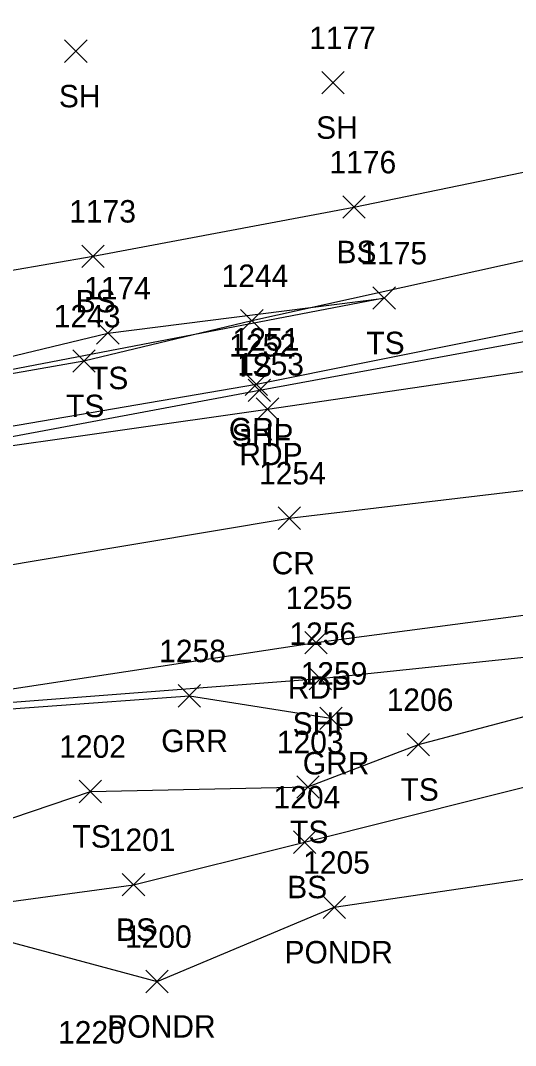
# Model space of a CAD drawing. Extents: x 1497084 to 1499861, y 734741 to 735567.
# Drawn here: x 1498376.8 to 1498420.9, y 735270.8 to 735362.1 of the extents above; entities that cross this region are included whole.
import ezdxf

# ---------------------------------------------------------------- set-up
doc = ezdxf.new("R2010")
doc.units = 0
for name, color, linetype in [('L_A', 7, 'Continuous'), ('L_I', 7, 'Continuous'), ('L_TIC', 7, 'Continuous'), ('LAWE', 7, 'Continuous'), ('LELB', 7, 'Continuous'), ('P_A', 7, 'Continuous'), ('P_I', 7, 'Continuous'), ('P_TIC', 7, 'Continuous'), ('PET', 7, 'Continuous'), ('PRC', 7, 'Continuous'), ('PSP', 7, 'Continuous'), ('R_A', 7, 'Continuous'), ('R_I', 7, 'Continuous'), ('R_TIC', 7, 'Continuous'), ('RGR', 7, 'Continuous')]:
    doc.layers.add(name, color=color, linetype=linetype)

msp = doc.modelspace()

# ---------------------------------------------------------------- linework, layer by layer
at = {"layer": 'L_TIC'}
for points in [[(1498380.723, 735358.388), (1498382.723, 735360.388)], [(1498382.723, 735358.388), (1498380.723, 735360.388)], [(1498403.65, 735355.584), (1498405.65, 735357.584)], [(1498405.65, 735355.584), (1498403.65, 735357.584)], [(1498405.509, 735344.506), (1498407.509, 735346.506)], [(1498407.509, 735344.506), (1498405.509, 735346.506)], [(1498382.259, 735340.124), (1498384.259, 735342.124)], [(1498384.259, 735340.124), (1498382.259, 735342.124)], [(1498408.205, 735336.398), (1498410.205, 735338.398)], [(1498410.205, 735336.398), (1498408.205, 735338.398)], [(1498396.406, 735334.385), (1498398.406, 735336.385)], [(1498398.406, 735334.385), (1498396.406, 735336.385)], [(1498383.577, 735333.278), (1498385.577, 735335.278)], [(1498385.577, 735333.278), (1498383.577, 735335.278)], [(1498381.446, 735330.791), (1498383.446, 735332.791)], [(1498383.446, 735330.791), (1498381.446, 735332.791)], [(1498411.25, 735296.618), (1498413.25, 735298.618)], [(1498413.25, 735296.618), (1498411.25, 735298.618)], [(1498382.016, 735292.443), (1498384.016, 735294.443)], [(1498384.016, 735292.443), (1498382.016, 735294.443)], [(1498401.409, 735292.849), (1498403.409, 735294.849)], [(1498403.409, 735292.849), (1498401.409, 735294.849)], [(1498401.115, 735287.931), (1498403.115, 735289.931)], [(1498403.115, 735287.931), (1498401.115, 735289.931)], [(1498385.861, 735284.137), (1498387.861, 735286.137)], [(1498387.861, 735284.137), (1498385.861, 735286.137)], [(1498403.752, 735282.124), (1498405.752, 735284.124)], [(1498405.752, 735282.124), (1498403.752, 735284.124)], [(1498387.96, 735275.515), (1498389.96, 735277.515)], [(1498389.96, 735275.515), (1498387.96, 735277.515)]]:
    msp.add_lwpolyline(points, dxfattribs=at)
at = {"layer": 'LAWE'}
msp.add_lwpolyline([(1498330.708, 735294.208), (1498340.697, 735295.582), (1498347.808, 735289.734), (1498355.835, 735283.797), (1498360.889, 735284.044), (1498388.96, 735276.515), (1498404.752, 735283.124), (1498435.911, 735287.743), (1498448.584, 735273.781), (1498443.339, 735255.806), (1498425.709, 735252.418), (1498412.053, 735248.321), (1498401.028, 735256.308), (1498395.487, 735265.648), (1498382.914, 735267.989), (1498367.49, 735259.738), (1498377.453, 735246.793), (1498383.142, 735228.324)], dxfattribs=at)
at = {"layer": 'LELB'}
for points in [[(1498337.56, 735327.025), (1498345.071, 735328.797), (1498360.02, 735336.053), (1498371.933, 735339.178), (1498383.259, 735341.124), (1498406.509, 735345.506), (1498447.671, 735353.973), (1498496.97, 735359.088), (1498555.389, 735373.271), (1498586.789, 735381.804), (1498595.746, 735372.636), (1498613.846, 735375.408), (1498671.762, 735381.92), (1498728.965, 735390.652), (1498788.671, 735399.739), (1498809.304, 735404.433), (1498807.972, 735434.197)], [(1498337.344, 735322.858), (1498344.97, 735324.745), (1498384.577, 735334.278), (1498409.205, 735337.398), (1498355.01, 735326.99), (1498382.446, 735331.791), (1498397.406, 735335.385), (1498428.619, 735342.289), (1498447.367, 735348.534), (1498497.982, 735350.736), (1498557.566, 735362.025), (1498577.341, 735369.5), (1498587.414, 735365.448), (1498611.954, 735369.89), (1498672.203, 735377.517), (1498729.566, 735386.751), (1498788.987, 735396.464), (1498814.154, 735401.685), (1498836.019, 735409.818), (1498851.622, 735410.693)], [(1498348.468, 735290.662), (1498349.296, 735292.118), (1498356.634, 735289.995), (1498367.396, 735288.155), (1498383.016, 735293.443), (1498402.409, 735293.849), (1498412.25, 735297.618), (1498434.814, 735303.591), (1498479.542, 735310.526), (1498504.668, 735314.809), (1498560.972, 735322.474), (1498619.672, 735330.556), (1498677.124, 735338.581), (1498739.343, 735349.098), (1498794.83, 735357.086), (1498843.562, 735364.403), (1498863.08, 735369.391)], [(1498347.808, 735289.734), (1498349.192, 735291.091), (1498355.192, 735287.185), (1498360.889, 735284.044), (1498368.956, 735282.699), (1498386.861, 735285.137), (1498402.115, 735288.931), (1498434.544, 735297.051), (1498479.168, 735305.56), (1498505.43, 735311.828), (1498561.532, 735319.258), (1498619.714, 735327.595), (1498677.773, 735335.72), (1498739.773, 735346.921), (1498794.896, 735353.463), (1498843.96, 735361.064), (1498867.571, 735365.181)]]:
    msp.add_lwpolyline(points, dxfattribs=at)
at = {"layer": 'P_TIC'}
for points in [[(1498397.081, 735328.187), (1498399.081, 735330.187)], [(1498399.081, 735328.187), (1498397.081, 735330.187)], [(1498397.802, 735326.496), (1498399.802, 735328.496)], [(1498399.802, 735326.496), (1498397.802, 735328.496)], [(1498399.743, 735316.79), (1498401.743, 735318.79)], [(1498401.743, 735316.79), (1498399.743, 735318.79)], [(1498402.131, 735305.703), (1498404.131, 735307.703)], [(1498404.131, 735305.703), (1498402.131, 735307.703)], [(1498402.505, 735302.499), (1498404.505, 735304.499)], [(1498404.505, 735302.499), (1498402.505, 735304.499)]]:
    msp.add_lwpolyline(points, dxfattribs=at)
at = {"layer": 'PET'}
for points in [[(1498338.165, 735318.882), (1498357.922, 735321.689), (1498398.802, 735327.496), (1498451.3, 735335.225), (1498500.844, 735343.241), (1498558.124, 735351.585), (1498613.705, 735360.595), (1498673.075, 735369.219), (1498732.204, 735378.982), (1498789.956, 735387.815), (1498838.316, 735395.911), (1498888.985, 735404.303)], [(1498338.165, 735318.882), (1498339.87, 735308.098), (1498341.541, 735297.196), (1498360.209, 735300.184), (1498403.131, 735306.703), (1498454.967, 735313.532), (1498504.375, 735320.924), (1498560.617, 735329.108), (1498618.152, 735338.15), (1498676.466, 735346.785), (1498736.788, 735356.316), (1498793.849, 735365.136), (1498842.44, 735373.21), (1498892.667, 735381.868)]]:
    msp.add_lwpolyline(points, dxfattribs=at)
at = {"layer": 'PRC'}
msp.add_lwpolyline([(1498339.87, 735308.098), (1498359.701, 735310.919), (1498400.743, 735317.79), (1498454.013, 735324.129), (1498502.48, 735331.982), (1498559.278, 735340.308), (1498615.274, 735349.361), (1498674.884, 735357.799), (1498734.125, 735367.052), (1498791.712, 735376.051), (1498839.889, 735384.369), (1498890.74, 735392.787)], dxfattribs=at)
at = {"layer": 'PSP'}
for points in [[(1498357.922, 735321.689), (1498398.081, 735329.187), (1498452.341, 735339.165), (1498499.614, 735346.687), (1498557.866, 735356.087), (1498612.391, 735365.432), (1498672.544, 735374.021), (1498730.824, 735383.147), (1498789.681, 735392.14), (1498809.844, 735395.769), (1498833.802, 735399.851), (1498855.601, 735403.687)], [(1498360.209, 735300.184), (1498403.505, 735303.499), (1498455.725, 735308.977), (1498504.765, 735316.344), (1498560.606, 735324.722), (1498619.041, 735333.453), (1498677.107, 735341.572), (1498738.317, 735351.548), (1498794.377, 735360.626), (1498843.609, 735368.572), (1498860.461, 735371.228)]]:
    msp.add_lwpolyline(points, dxfattribs=at)
at = {"layer": 'R_TIC'}
for points in [[(1498396.818, 735328.72), (1498398.818, 735330.72)], [(1498398.818, 735328.72), (1498396.818, 735330.72)], [(1498390.841, 735300.959), (1498392.841, 735302.959)], [(1498392.841, 735300.959), (1498390.841, 735302.959)], [(1498403.458, 735298.963), (1498405.458, 735300.963)], [(1498405.458, 735298.963), (1498403.458, 735300.963)]]:
    msp.add_lwpolyline(points, dxfattribs=at)
at = {"layer": 'RGR'}
for points in [[(1498338.329, 735319.531), (1498397.818, 735329.72), (1498437.964, 735337.775), (1498448.189, 735342.894)], [(1498341.606, 735296.979), (1498360.793, 735299.518), (1498365.752, 735300.05), (1498391.841, 735301.959), (1498404.458, 735299.963)]]:
    msp.add_lwpolyline(points, dxfattribs=at)

# ---------------------------------------------------------------- texts
at = {"layer": 'L_A'}
for s, p in [('SH', (1498380.211, 735354.388)), ('SH', (1498403.139, 735351.584)), ('BS', (1498404.95, 735340.506)), ('BS', (1498381.7, 735336.124)), ('TS', (1498407.614, 735332.398)), ('TS', (1498395.816, 735330.385)), ('TS', (1498382.986, 735329.278)), ('TS', (1498380.856, 735326.791)), ('TS', (1498410.659, 735292.618)), ('TS', (1498400.818, 735288.849)), ('TS', (1498381.425, 735288.443)), ('BS', (1498400.556, 735283.931)), ('BS', (1498385.302, 735280.137)), ('PONDR', (1498400.319, 735278.124)), ('PONDR', (1498384.527, 735271.515))]:
    msp.add_text(s, height=2, dxfattribs=at).set_placement(p)
at = {"layer": 'L_I'}
for s, p in [('1177', (1498402.524, 735359.584)), ('1176', (1498404.328, 735348.506)), ('1173', (1498381.133, 735344.124)), ('1175', (1498407.079, 735340.398)), ('1244', (1498394.713, 735338.385)), ('1174', (1498382.451, 735337.278)), ('1243', (1498379.753, 735334.791)), ('1206', (1498409.423, 735300.618)), ('1203', (1498399.637, 735296.849)), ('1202', (1498380.244, 735296.443)), ('1204', (1498399.344, 735291.931)), ('1201', (1498384.656, 735288.137)), ('1205', (1498401.98, 735286.124)), ('1200', (1498386.102, 735279.515)), ('1220', (1498380.135, 735270.989))]:
    msp.add_text(s, height=2, dxfattribs=at).set_placement(p)
at = {"layer": 'P_A'}
for s, p in [('SHP', (1498395.616, 735324.187)), ('RDP', (1498396.29, 735322.496)), ('CR', (1498399.176, 735312.79)), ('RDP', (1498400.619, 735301.703)), ('SHP', (1498401.041, 735298.499))]:
    msp.add_text(s, height=2, dxfattribs=at).set_placement(p)
at = {"layer": 'P_I'}
for s, p in [('1252', (1498395.388, 735332.187)), ('1253', (1498396.109, 735330.496)), ('1254', (1498398.05, 735320.79)), ('1255', (1498400.438, 735309.703)), ('1256', (1498400.757, 735306.499))]:
    msp.add_text(s, height=2, dxfattribs=at).set_placement(p)
at = {"layer": 'R_A'}
for s, p in [('GRL', (1498395.362, 735324.72)), ('GRR', (1498389.33, 735296.959)), ('GRR', (1498401.946, 735294.963))]:
    msp.add_text(s, height=2, dxfattribs=at).set_placement(p)
at = {"layer": 'R_I'}
for s, p in [('1251', (1498395.692, 735332.72)), ('1258', (1498389.149, 735304.959)), ('1259', (1498401.757, 735302.963))]:
    msp.add_text(s, height=2, dxfattribs=at).set_placement(p)

doc.saveas('drawing.dxf')
